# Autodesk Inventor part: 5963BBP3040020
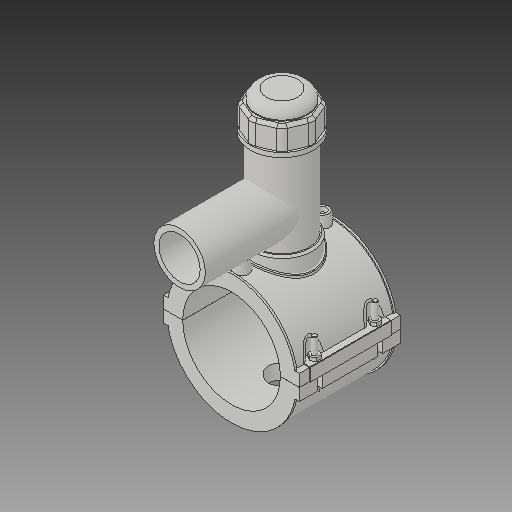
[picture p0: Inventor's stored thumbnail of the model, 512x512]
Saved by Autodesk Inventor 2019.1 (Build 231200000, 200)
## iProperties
Created: 2017-07
Part Number: 5963BBP3040020
Material: Generic
Description: PLASSON TAPPING SADDLE 4''IPS x 2''IPS
Document SubType Name: Modeling
Designer: KIM
Density: 1 g/cm^3
Appearance: Default
Author: KIM
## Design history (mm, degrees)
derived "5963BBP_5963BUP.ipt"
feature "Solid1::5963BBP_5963BUP.ipt"
feature "Solid2::5963BBP_5963BUP.ipt"
feature "Solid3::5963BBP_5963BUP.ipt"
tag "TaggingFeature1"
body "Solid1"
body "Solid2"
body "Solid3"
other parameters: "d0" = 114.1, "d2" = 159.004, "d3" = 28.525, "d4" = 118.11, "d5" = 0, "d6" = 0.1, "d8" = 0, "d19" = 6, "d20" = 6, "d21" = 70.866, "d23" = 0, "d24" = 35.433, "d26" = 0, "d27" = 3, "d28" = 3, "d29" = 3, "d30" = 38.03333, "d31" = 6, "d32" = 0, "d33" = 0, "d34" = 0.6, "d40" = 77.1316, "d41" = 74.165, "d43" = 0, "d45" = 0, "d47" = 145.031, "d70" = 15, "d72" = 0, "d73" = 6, "d75" = 5, "d76" = 0, "d77" = 5.705, "d78" = 87.05, "d79" = 15, "d80" = 47.244, "d82" = 5 deg, "d84" = 4, "d85" = 14, "d86" = 0, "d87" = 3, "d88" = 0, "d89" = 1, "d90" = 1, "d91" = 94.488, "d92" = 0, "d93" = 0.5, "d94" = 60.05263, "d96" = 151.2966, "d97" = 2.3622, "d98" = 0, "d102" = 1.141, "d120" = 140 deg, "d121" = 24.228, "d122" = 20 deg, "d123" = 296.66, "d124" = 88.998, "d126" = 0, "d143" = 117.523, "d145" = 26.33077, "d149" = 1.7115, "d150" = 28.96385, "d153" = 118.11, "d154" = 0, "d156" = 74.165, "d157" = 160 deg, "d159" = 6.846, "d161" = 1.7115, "d162" = 70.866, "d163" = 0, "d164" = 57.05, "d167" = 11.41, "d168" = 72.3561, "d170" = 3.2805, "d172" = 0, "d173" = 1, "d175" = 57.05, "d176" = 20 deg, "d177" = 7.987, "d178" = 34.23, "d180" = 0, "d183" = 13.692, "d184" = 6.3896, "d185" = 38.38575, "d186" = 38.38575, "d187" = 74.165, "d188" = 10.269, "d189" = 7.987, "d190" = 0, "d191" = 111.2475, "d193" = 6.9984, "d194" = 4.13385, "d195" = 90 deg, "d197" = 0, "d199" = 0, "d200" = 17.115, "d202" = 0, "d203" = 177.038, "d204" = 70.45675, "d205" = 51.9155, "d206" = 63.04025, "d207" = 132.7785, "d208" = 138.08964, "d209" = 164.64534, "d210" = 63.7819, "d211" = 74.165, "d212" = 59.332, "d213" = 31.4766, "d216" = 0, "d217" = 11.41, "d218" = 11.41, "d219" = 2.282, "d222" = 114.1, "d224" = 0, "d225" = 65.024, "d226" = 60.1, "d227" = 48.08, "d228" = 119.888, "d230" = 3.423, "d_" = 114.1, "B_" = 159.004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
